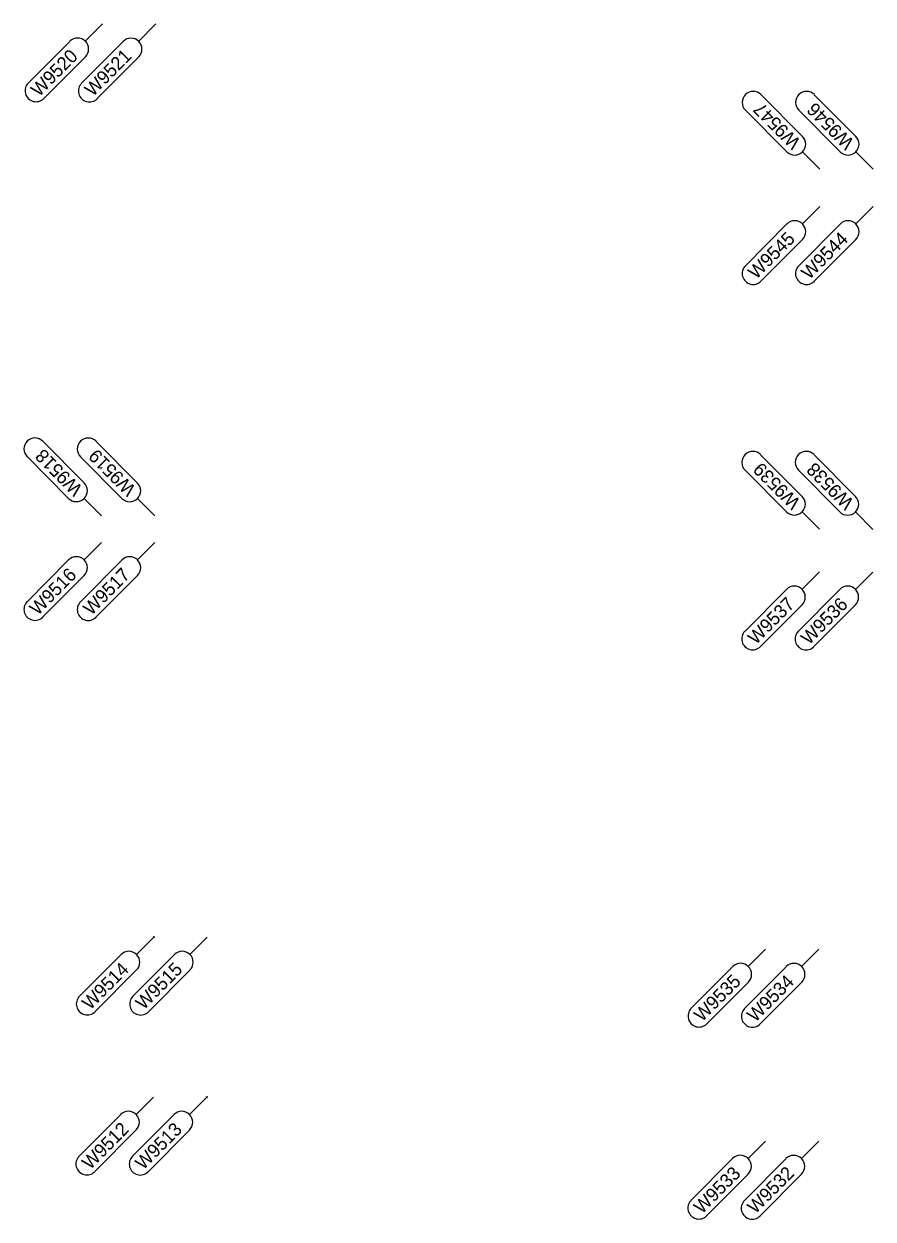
# Model space of a CAD drawing. Extents: x 12479652 to 12487250, y 9842710 to 9846560.
# Drawn here: x 12483665.5 to 12483745, y 9844379.3 to 9844491.3 of the extents above; entities that cross this region are included whole.
import ezdxf

# ---------------------------------------------------------------- set-up
doc = ezdxf.new("R2010")
doc.units = 0
doc.layers.add('Default', color=7, linetype='Continuous')
doc.layers.add('TextAlignmentLrg', color=7, linetype='Continuous')

msp = doc.modelspace()

# ---------------------------------------------------------------- linework, layer by layer
at = {"layer": 'Default'}
for p, q in [((12483672.85, 9844491.32), (12483671.23, 9844489.69)), ((12483677.85, 9844491.31), (12483676.23, 9844489.68)), ((12483665.89, 9844485.77), (12483669.78, 9844489.68)), ((12483670.89, 9844485.76), (12483674.78, 9844489.67)), ((12483671.24, 9844488.24), (12483667.35, 9844484.32)), ((12483676.24, 9844488.22), (12483672.35, 9844484.31)), ((12483738.43, 9844480.77), (12483734.54, 9844484.69)), ((12483743.43, 9844480.77), (12483739.54, 9844484.68)), ((12483733.08, 9844483.24), (12483736.97, 9844479.33)), ((12483738.08, 9844483.24), (12483741.97, 9844479.32)), ((12483740.04, 9844477.69), (12483738.42, 9844479.32)), ((12483745.04, 9844477.69), (12483743.42, 9844479.32)), ((12483740.04, 9844474.19), (12483738.42, 9844472.56)), ((12483745.04, 9844474.19), (12483743.42, 9844472.56)), ((12483733.08, 9844468.64), (12483736.97, 9844472.56)), ((12483738.08, 9844468.64), (12483741.97, 9844472.55)), ((12483738.42, 9844471.11), (12483734.53, 9844467.2)), ((12483743.42, 9844471.11), (12483739.53, 9844467.19)), ((12483671.13, 9844448.28), (12483667.24, 9844452.2)), ((12483676.13, 9844448.27), (12483672.24, 9844452.18)), ((12483738.39, 9844447.02), (12483734.51, 9844450.93)), ((12483743.39, 9844447.02), (12483739.51, 9844450.93)), ((12483665.78, 9844450.75), (12483669.67, 9844446.84)), ((12483670.78, 9844450.74), (12483674.67, 9844446.82)), ((12483733.05, 9844449.49), (12483736.94, 9844445.58)), ((12483738.05, 9844449.48), (12483741.94, 9844445.57)), ((12483672.75, 9844445.2), (12483671.12, 9844446.83)), ((12483677.75, 9844445.19), (12483676.12, 9844446.82)), ((12483740.01, 9844443.94), (12483738.39, 9844445.57)), ((12483745.01, 9844443.93), (12483743.39, 9844445.57)), ((12483672.74, 9844442.7), (12483671.12, 9844441.07)), ((12483677.74, 9844442.69), (12483676.12, 9844441.06)), ((12483665.78, 9844437.15), (12483669.67, 9844441.06)), ((12483670.78, 9844437.14), (12483674.67, 9844441.05)), ((12483740.01, 9844439.94), (12483738.39, 9844438.31)), ((12483745.01, 9844439.93), (12483743.39, 9844438.3)), ((12483671.12, 9844439.62), (12483667.23, 9844435.71)), ((12483676.12, 9844439.61), (12483672.23, 9844435.69)), ((12483733.05, 9844434.39), (12483736.94, 9844438.3)), ((12483738.05, 9844434.39), (12483741.94, 9844438.3)), ((12483738.39, 9844436.86), (12483734.5, 9844432.94)), ((12483743.39, 9844436.85), (12483739.5, 9844432.94)), ((12483677.65, 9844405.71), (12483676.03, 9844404.08)), ((12483682.65, 9844405.7), (12483681.03, 9844404.07)), ((12483670.69, 9844400.16), (12483674.58, 9844404.08)), ((12483675.69, 9844400.16), (12483679.58, 9844404.07)), ((12483734.97, 9844404.57), (12483733.35, 9844402.94)), ((12483739.97, 9844404.57), (12483738.35, 9844402.94)), ((12483728.01, 9844399.03), (12483731.9, 9844402.94)), ((12483733.01, 9844399.02), (12483736.9, 9844402.93)), ((12483676.04, 9844402.63), (12483672.15, 9844398.72)), ((12483681.04, 9844402.62), (12483677.15, 9844398.71)), ((12483733.36, 9844401.49), (12483729.47, 9844397.58)), ((12483738.36, 9844401.48), (12483734.47, 9844397.57)), ((12483677.62, 9844390.71), (12483676, 9844389.08)), ((12483682.62, 9844390.7), (12483681, 9844389.07)), ((12483670.66, 9844385.16), (12483674.55, 9844389.08)), ((12483675.66, 9844385.16), (12483679.55, 9844389.07)), ((12483676, 9844387.63), (12483672.11, 9844383.72)), ((12483681, 9844387.62), (12483677.11, 9844383.71)), ((12483734.95, 9844386.57), (12483733.33, 9844384.94)), ((12483739.95, 9844386.57), (12483738.33, 9844384.94)), ((12483727.99, 9844381.03), (12483731.88, 9844384.94)), ((12483732.99, 9844381.02), (12483736.88, 9844384.93)), ((12483733.34, 9844383.49), (12483729.45, 9844379.58)), ((12483738.34, 9844383.48), (12483734.45, 9844379.57))]:
    msp.add_line(p, q, dxfattribs=at)
for centre, start, end in [((12483670.51, 9844488.96), 315.1702, 135.1702), ((12483675.51, 9844488.95), 315.1702, 135.1702), ((12483666.62, 9844485.05), 135.1702, 315.1702), ((12483671.62, 9844485.03), 135.1702, 315.1702), ((12483733.81, 9844483.96), 44.8253, 224.8253), ((12483738.81, 9844483.96), 44.8253, 224.8253), ((12483737.7, 9844480.05), 224.8253, 44.8253), ((12483742.7, 9844480.05), 224.8253, 44.8253), ((12483737.7, 9844471.83), 315.1702, 135.1702), ((12483742.7, 9844471.83), 315.1702, 135.1702), ((12483733.81, 9844467.92), 135.1702, 315.1702), ((12483738.81, 9844467.92), 135.1702, 315.1702), ((12483666.51, 9844451.47), 44.8253, 224.8253), ((12483671.51, 9844451.46), 44.8253, 224.8253), ((12483733.78, 9844450.21), 44.8253, 224.8253), ((12483738.78, 9844450.21), 44.8253, 224.8253), ((12483670.4, 9844447.56), 224.8253, 44.8253), ((12483675.4, 9844447.55), 224.8253, 44.8253), ((12483737.67, 9844446.3), 224.8253, 44.8253), ((12483742.67, 9844446.29), 224.8253, 44.8253), ((12483670.4, 9844440.34), 315.1702, 135.1702), ((12483675.4, 9844440.33), 315.1702, 135.1702), ((12483737.66, 9844437.58), 315.1702, 135.1702), ((12483742.66, 9844437.58), 315.1702, 135.1702), ((12483666.51, 9844436.43), 135.1702, 315.1702), ((12483671.51, 9844436.42), 135.1702, 315.1702), ((12483733.77, 9844433.67), 135.1702, 315.1702), ((12483738.77, 9844433.66), 135.1702, 315.1702), ((12483675.31, 9844403.35), 315.1702, 135.1702), ((12483680.31, 9844403.35), 315.1702, 135.1702), ((12483732.63, 9844402.22), 315.1702, 135.1702), ((12483737.63, 9844402.21), 315.1702, 135.1702), ((12483671.42, 9844399.44), 135.1702, 315.1702), ((12483676.42, 9844399.43), 135.1702, 315.1702), ((12483728.74, 9844398.3), 135.1702, 315.1702), ((12483733.74, 9844398.29), 135.1702, 315.1702), ((12483675.27, 9844388.35), 315.1702, 135.1702), ((12483680.27, 9844388.35), 315.1702, 135.1702), ((12483671.38, 9844384.44), 135.1702, 315.1702), ((12483676.38, 9844384.43), 135.1702, 315.1702), ((12483732.61, 9844384.22), 315.1702, 135.1702), ((12483737.61, 9844384.21), 315.1702, 135.1702), ((12483728.72, 9844380.3), 135.1702, 315.1702), ((12483733.72, 9844380.29), 135.1702, 315.1702)]:
    msp.add_arc(centre, 1.03, start, end, dxfattribs=at)
at = {"layer": 'TextAlignmentLrg'}
for centre in [(12483677.65, 9844405.71), (12483682.62, 9844390.7)]:
    msp.add_circle(centre, 0.05, dxfattribs=at)

# ---------------------------------------------------------------- texts
at = {"layer": 'Default'}
for s, rotation, p in [('W9520', 45.1702, (12483666.89, 9844484.42)), ('W9521', 45.1702, (12483671.93, 9844484.44)), ('W9547', 134.8253, (12483738.34, 9844480.31)), ('W9546', 134.8253, (12483743.35, 9844480.29)), ('W9545', 45.1702, (12483734.09, 9844467.31)), ('W9544', 45.1702, (12483739.07, 9844467.28)), ('W9518', 134.8253, (12483671.05, 9844447.81)), ('W9519', 134.8253, (12483676.05, 9844447.8)), ('W9539', 134.8253, (12483738.32, 9844446.55)), ('W9538', 134.8253, (12483743.32, 9844446.54)), ('W9516', 45.1702, (12483666.77, 9844435.8)), ('W9517', 45.1702, (12483671.79, 9844435.8)), ('W9537', 45.1702, (12483734.06, 9844433.05)), ('W9536', 45.1702, (12483739.04, 9844433.03)), ('W9514', 45.1702, (12483671.68, 9844398.81)), ('W9515', 45.1702, (12483676.7, 9844398.82)), ('W9535', 45.1702, (12483729.02, 9844397.69)), ('W9534', 45.1702, (12483734, 9844397.66)), ('W9512', 45.1702, (12483671.68, 9844383.83)), ('W9513', 45.1702, (12483676.66, 9844383.81)), ('W9533', 45.1702, (12483729, 9844379.68)), ('W9532', 45.1702, (12483734.01, 9844379.69))]:
    msp.add_text(s, height=1.25, rotation=rotation, dxfattribs=at).set_placement(p)

doc.saveas('drawing.dxf')
